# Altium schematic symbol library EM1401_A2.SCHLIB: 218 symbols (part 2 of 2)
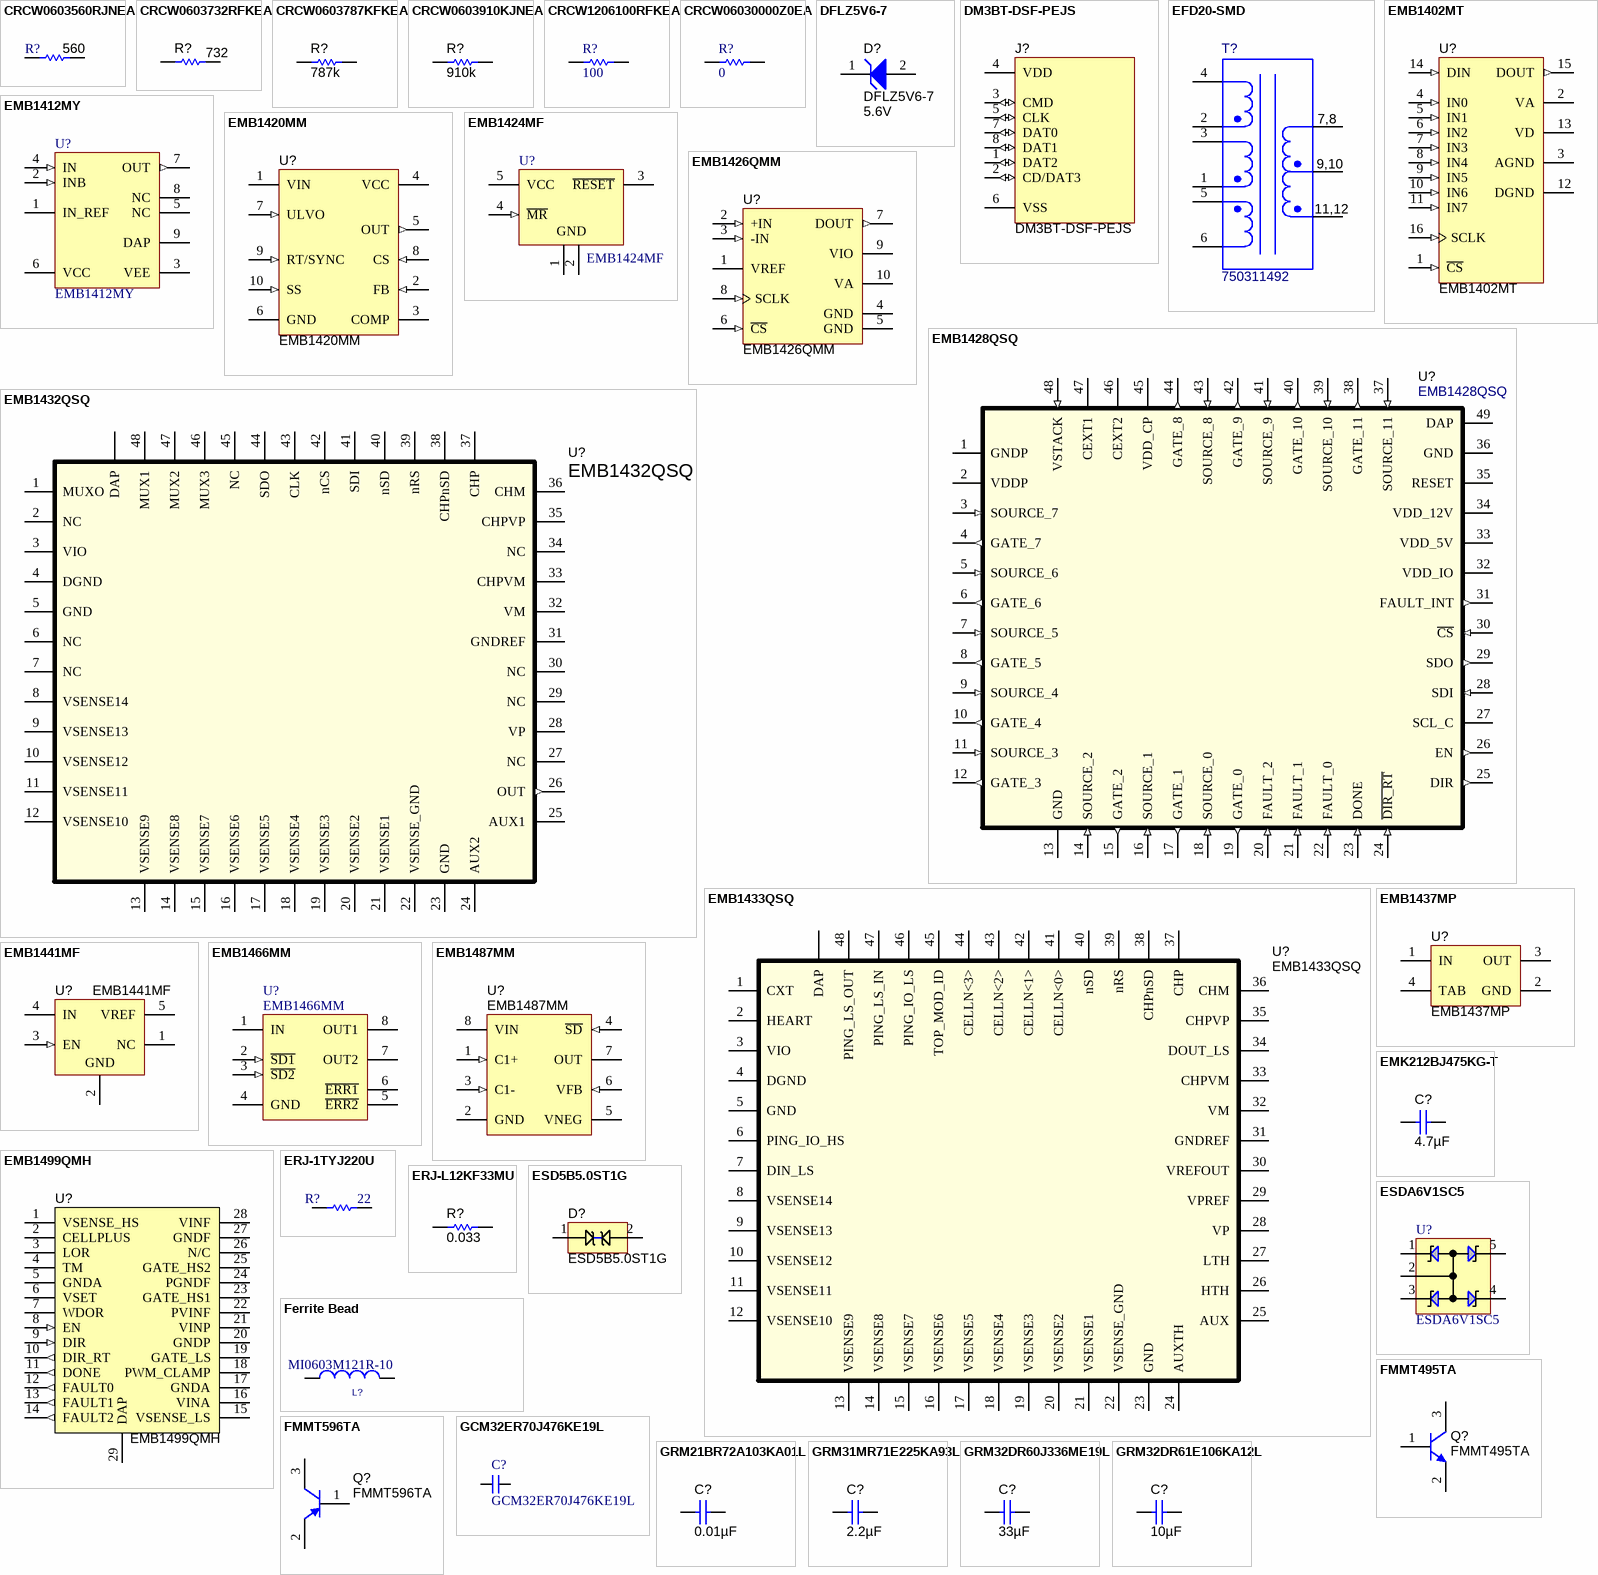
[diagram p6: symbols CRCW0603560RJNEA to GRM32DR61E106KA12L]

## EMB1433QSQ
designator U?
Battery Stack Protection WCOMP; Manufacturer: National Semiconductor; CompType: Used in BOM report; SymbolVersion: 100509; SymbolCreator: cwiosc
footprint sqa48b (QFN, 48-Leads, Body 7x7mm, Pitch 0.5mm, NSC Recommended)
pins: 1 CXT, 2 HEART, 3 VIO, 4 DGND, 5 GND, 6 PING_IO_HS, 7 DIN_LS, 8 VSENSE14, 9 VSENSE13, 10 VSENSE12, 11 VSENSE11, 12 VSENSE10, 13 VSENSE9, 14 VSENSE8, 15 VSENSE7, 16 VSENSE6, 17 VSENSE5, 18 VSENSE4, 19 VSENSE3, 20 VSENSE2, 21 VSENSE1, 22 VSENSE_GND, 23 GND, 24 AUXTH, 25 AUX, 26 HTH, 27 LTH, 28 VP, 29 VPREF, 30 VREFOUT, 31 GNDREF, 32 VM, 33 CHPVM, 34 DOUT_LS, 35 CHPVP, 36 CHM, 37 CHP, 38 CHPnSD, 39 nRS, 40 nSD, 41 CELLN<0>, 42 CELLN<1>, 43 CELLN<2>, 44 CELLN<3>, 45 TOP_MOD_ID, 46 PING_IO_LS, 47 PING_LS_IN, 48 PING_LS_OUT, 49 DAP

## EMB1437MP
designator U?
500 mA Low Dropout Regulator; Manufacturer: National Semiconductor; CompType: LDO IC; PowerWise: N
footprint MP04A_N (SOT223, 4-Leads, Body 6.5x3.5mm, Pitch 2.3mm, Lead Span 7mm, IPC Medium Density)
footprint MP04A_L (SOT223, 4-Leads, Body 6.5x3.5mm, Pitch 2.3mm, Lead Span 7mm, IPC High Density)
footprint MP04A_M (SOT223, 4-Leads, Body 6.5x3.5mm, Pitch 2.3mm, Lead Span 7mm, IPC Low Density)
pins: 1 IN (power), 2 GND (power), 3 OUT (power), 4 TAB (power)

## EMB1441MF
designator U?
SOT-23 Precision Low Dropout Voltage Reference; Manufacturer: National Semiconductor; CompType: Voltage Reference IC; PowerWise: Y
footprint MF05A_N (SOT23, 5-Leads, Body 2.9x1.6mm, Pitch 0.95mm, Lead Span 2.8mm, IPC Medium Density)
footprint MF05A_L (SOT23, 5-Leads, Body 2.9x1.6mm, Pitch 0.95mm, Lead Span 2.8mm, IPC High Density)
footprint MF05A_M (SOT23, 5-Leads, Body 2.9x1.6mm, Pitch 0.95mm, Lead Span 2.8mm, IPC Low Density)
pins: 1 NC, 2 GND (power), 3 EN (in), 4 IN (power), 5 VREF (power)

## EMB1466MM
designator U?
Dual 150mA Ultra Low-Dropout Regulator; Manufacturer: National Semiconductor; CompType: LDO IC; PowerWise: N
footprint MUA08A_N (TSOP, 8-Leads, Body 3x3mm, Pitch 0.65mm, IPC Medium Density)
footprint MUA08A_L (TSOP, 8-Leads, Body 3x3mm, Pitch 0.65mm, IPC High Density)
footprint MUA08A_M (TSOP, 8-Leads, Body 3x3mm, Pitch 0.65mm, IPC Low Density)
pins: 1 IN (power), 2 ~{SD1} (in), 3 ~{SD2} (in), 4 GND (power), 5 ~{ERR2} (oc), 6 ~{ERR1} (oc), 7 OUT2 (power), 8 OUT1 (power)

## EMB1487MM
designator U?
Low Noise Regulated Switched Capacitor Voltage Inverter; Manufacturer: National Semiconductor; CompType: Switch Caps; PowerWise: N
footprint MUA08A_N (TSOP, 8-Leads, Body 3x3mm, Pitch 0.65mm, IPC Medium Density)
footprint MUA08A_L (TSOP, 8-Leads, Body 3x3mm, Pitch 0.65mm, IPC High Density)
footprint MUA08A_M (TSOP, 8-Leads, Body 3x3mm, Pitch 0.65mm, IPC Low Density)
pins: 1 C1+ (in), 2 GND (power), 3 C1- (in), 4 ~{SD} (in), 5 VNEG (power), 6 VFB (in), 7 OUT (power), 8 VIN (power)

## EMB1499QMH
designator U?
PWM Controller; Manufacturer: National Semiconductor; CompType: Used in BOM report; SymbolVersion: use current date i.e. 2008-05-20; SymbolCreator: Use LDAP id
footprint MXA28A_M (TSOP, 28-Leads, Body 9.7x4.4mm, Pitch 0.65mm, Exposed Pad, IPC Low Density)
pins: 1 VSENSE_HS, 2 CELLPLUS, 3 LOR, 4 TM, 5 GNDA, 6 VSET, 7 WDOR, 8 EN (in), 9 DIR (in), 10 DIR_RT (out), 11 DONE (out), 12 FAULT0 (out), 13 FAULT1 (out), 14 FAULT2 (out), 15 VSENSE_LS, 16 VINA, 17 GNDA, 18 PWM_CLAMP, 19 GATE_LS, 20 GNDP, 21 VINP, 22 PVINF, 23 GATE_HS1, 24 PGNDF, 25 GATE_HS2, 26 N/C, 27 GNDF, 28 VINF, 29 DAP

## EMK212BJ475KG-T
designator C?  value 4.7µF  (hidden comment: EMK212BJ475KG-T)
CAP, CERM, 4.7µF, 16V, +/-10%, X5R, 0805; Manufacturer: Taiyo Yuden; Cap_Case: 0805; Polarized: N; TaMax_C: 85; TaMin_C: -55; Tolerance_%: 10; VDC_V: 16; Cap_F: 4.7E-6; CompType: Capacitor
signal-integrity model Cap
simulation model Cap
footprint 0805_HV
footprint 0805
footprint 0805M
footprint 0805L
pins: 1, 2

## ERJ-1TYJ220U
designator R?  value 22  (hidden comment: ERJ-1TYJ220U)
22 Ohm 1%, 1W; Manufacturer: Panasonic; CompType: Resistor; Tolerance_%: 1; Res_Ohm: 100; Value_Code: R020; EIA_Code: ERJ
signal-integrity model Resistor
simulation model Resistor
footprint 2512M (Chip Resistor, Body 6.3x3.2mm, IPC Low Density)
footprint 2010L
footprint 2010
pins: 1, 2

## ERJ-L12KF33MU
designator R?  value 0.033  (hidden comment: ERJ-L12KF33MU)
RES, 0.033 ohm, 1%, 0.5W, 1812 SMD; Manufacturer: Panasonic; CompType: Resistor; Tolerance_%: 1; Power_W: 0.5; Value_Code: R033; EIA_Code: E96
signal-integrity model Resistor
simulation model Resistor
footprint 1812M
footprint 1812L
footprint 1812
pins: 1, 2

## ESD5B5.0ST1G
designator D?
TVS ESD BIDIRECT 5V SOD523; Manufacturer: ON Semiconductor; SymbolVersion: use current date i.e. 2008-05-20; SymbolCreator: Use LDAP id
footprint SOD523 TVS (SOD footpirnt - TVS ESD Bidirectional)
pins: 1, 2

## ESDA6V1SC5
designator U?
DIODE ARRAY ESD 6.1V Breakdown; Manufacturer: STMicroelectronics; CompType: ESD protection
footprint MF05A_M (SOT23, 5-Leads, Body 2.9x1.6mm, Pitch 0.95mm, Lead Span 2.8mm, IPC Low Density)
pins: 1 IO1, 2 IO2, 3 IO3, 4 IO4, 5 IO5

## Ferrite Bead
designator L?, comment MI0603M121R-10
Ferrite bead, 120mOhm, 2A, 0603; Manufacturer: Steward
footprint 0603
pins: 1, 2

## FMMT495TA
designator Q?
NPN, 1A, 150V; Manufacturer: Diodes Inc.; CompType: BJT; IcRated_A: 1; Vceo_V: 150; Vcesat1_V: 0.2; Value: 0.2V; PNP: 0
footprint SOT-23 (SOT23, 3-Leads, Body 2.9x1.3mm, Pitch 0.95mm, Lead Span 2.5mm, IPC Medium Density)
pins: 1 B, 2 E, 3 C

## FMMT596TA
designator Q?
PNP, 1.4A, 100V; Manufacturer: Diodes Inc; CompType: BJT; IcRated_A: 0.3; Vceo_V: 200; Vcesat1_V: 0.2; Value: 0.2V; PNP: 1; NPN: 0; Value1: 0.3A
footprint SOT-23 (SOT23, 3-Leads, Body 2.9x1.3mm, Pitch 0.95mm, Lead Span 2.5mm, IPC Medium Density)
pins: 1 B, 2 E, 3 C

## GCM32ER70J476KE19L
designator C?
CAP CER 47UF 6.3V X7R 1210; Manufacturer: Murata; CompType: Capacitor X7R
footprint 1210 (1210 STANDARD SIZE)
pins: 1, 2

## GRM21BR72A103KA01L
designator C?  ValueDisplayed: 0.01µF  (hidden comment: GRM21BR72A103KA01L)
CAP, CERM, 0.01uF, 100V, +/-10%, X7R, 0805; Manufacturer: MuRata; Cap_Case: 0805; Polarized: N; TaMax_C: 125; TaMin_C: -55; Tolerance_%: 10; VDC_V: 100; Cap_F: 0.00000001; CompType: Capacitor; U/M: EA
signal-integrity model Cap
simulation model Cap
footprint 0805_HV
footprint 0805
footprint 0805M
footprint 0805L
pins: 1, 2

## GRM31MR71E225KA93L
designator C?  ValueDisplayed: 2.2µF  (hidden comment: GRM31MR71E225KA93L)
CAP, CERM, 2.2uF, 25V, +/-10%, X7R, 1210; Manufacturer: MuRata; Cap_Case: 1210; Polarized: N; TaMax_C: 125; TaMin_C: -55; Tolerance_%: 10; VDC_V: 25; Cap_F: 0.0000022; CompType: Capacitor; U/M: EA
signal-integrity model Cap
simulation model Cap
footprint 1210
footprint 1210M
footprint 1210L
pins: 1, 2

## GRM32DR60J336ME19L
designator C?  ValueDisplayed: 33µF  (hidden comment: GRM32DR60J336ME19L)
CAP, CERM, 33uF, 6.3V, +/-20%, X5R, 1210; Manufacturer: MuRata; Cap_Case: 1210; ESR_Ohm: 0.006; Polarized: N; TaMax_C: 85; TaMin_C: -55; Tolerance_%: 20; VDC_V: 6.3; Cap_F: 0.000033; CompType: Capacitor; U/M: EA; Value1: 0.006 ohm
signal-integrity model Cap
simulation model Cap
footprint 1210
footprint 1210M
footprint 1210L
pins: 1, 2

## GRM32DR61E106KA12L
designator C?  ValueDisplayed: 10µF  (hidden comment: GRM32DR61E106KA12L)
CAP, CERM, 10uF, 25V, +/-10%, X5R, 1210; Manufacturer: MuRata; Cap_Case: 1210; Polarized: N; TaMax_C: 85; TaMin_C: -55; Tolerance_%: 10; VDC_V: 25; Cap_F: 0.00001; CompType: Capacitor; U/M: EA
signal-integrity model Cap
simulation model Cap
footprint 1210
footprint 1210M
footprint 1210L
pins: 1, 2

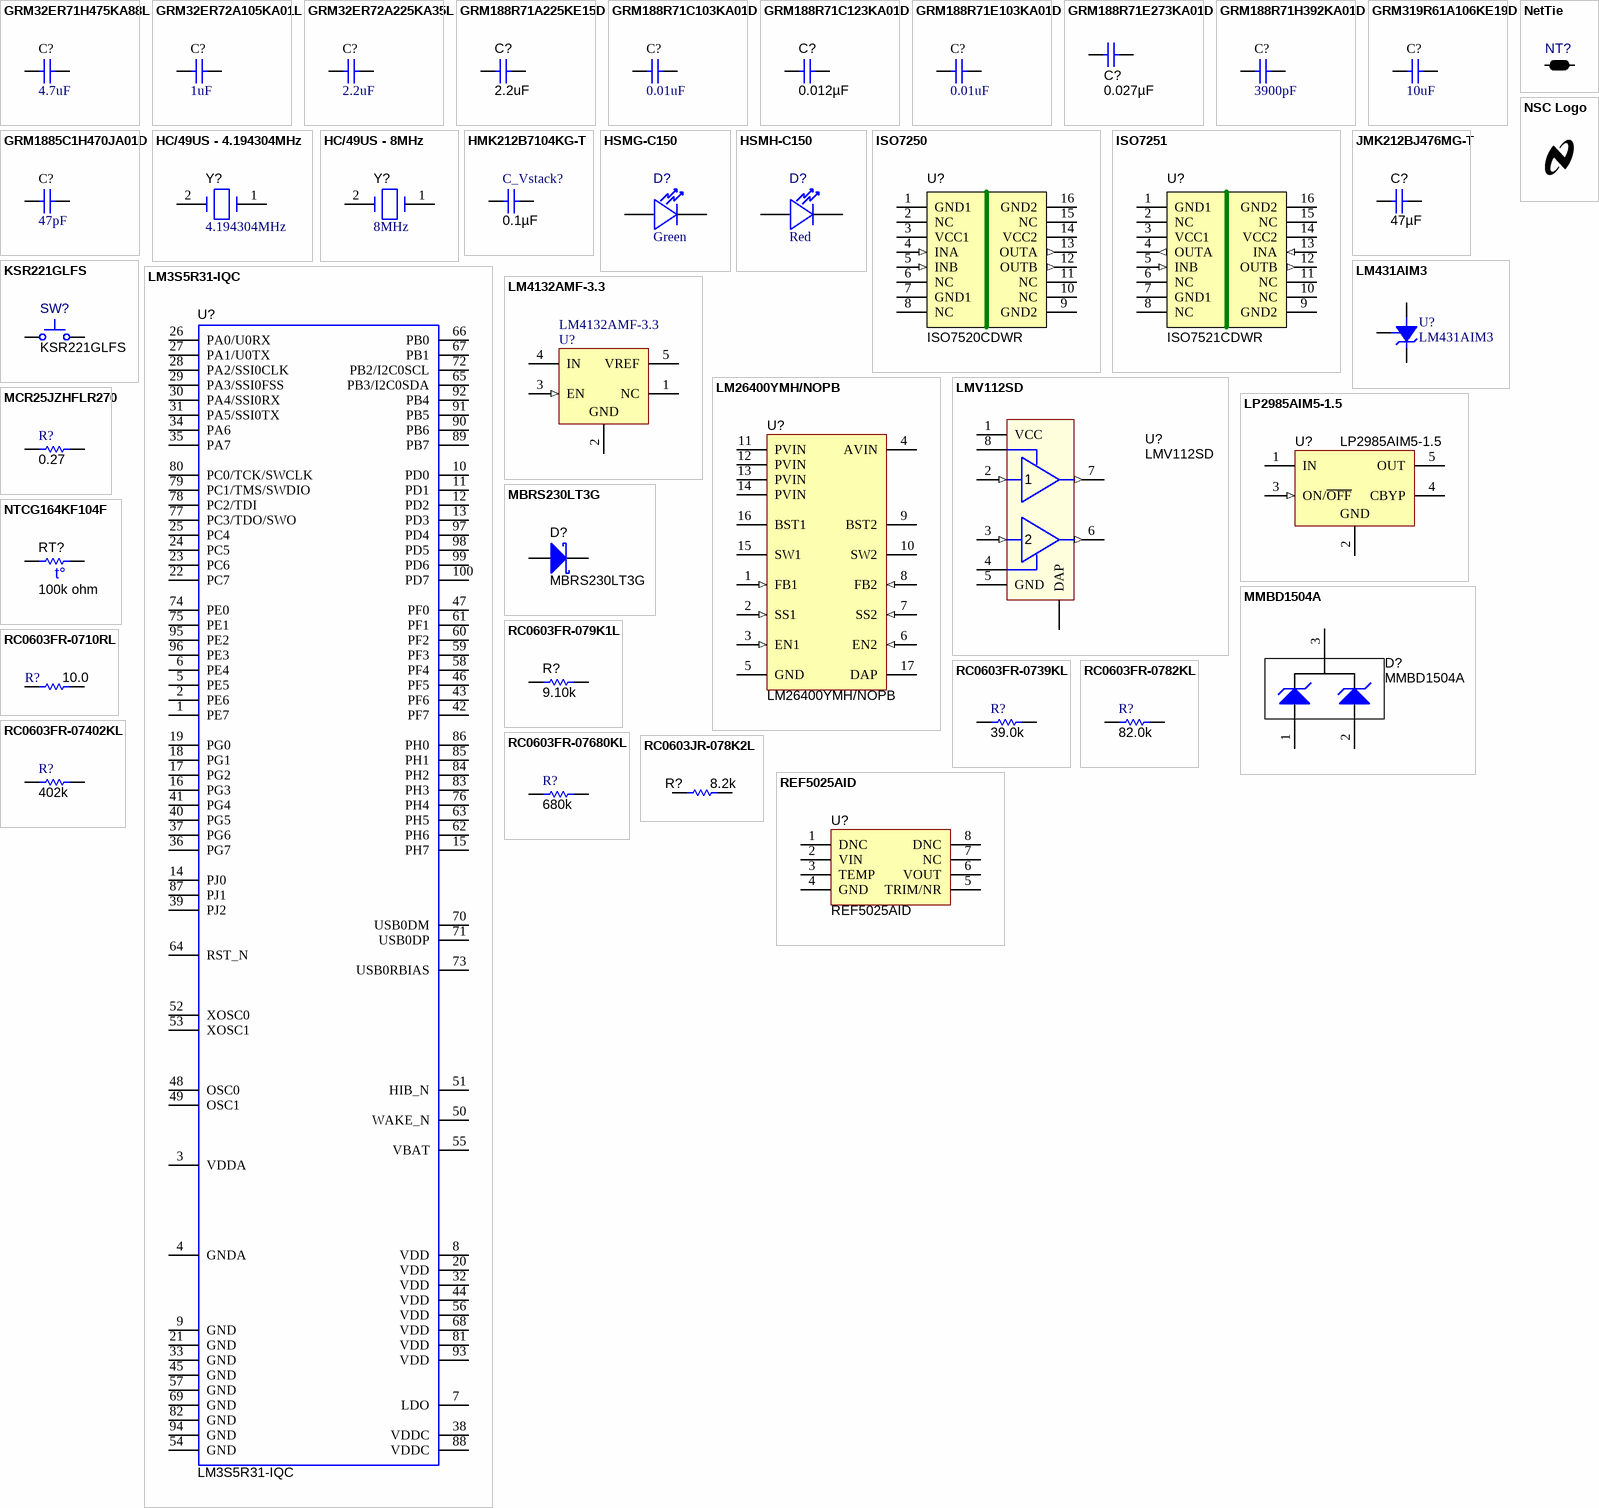
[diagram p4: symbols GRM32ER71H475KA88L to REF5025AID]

## GRM32ER71H475KA88L
designator C?  value 4.7uF  (hidden comment: GRM32ER71H475KA88L)
Ceramic, X7R, 50V, 10%; Manufacturer: MuRata; Cap_Case: 1210; ESR_Ohm: 0.002; Polarized: N; TaMax_C: 125; TaMin_C: -55; Tolerance_%: 10; VDC_V: 50; Cap_F: 4.7E-6; CompType: Capacitor; Value1: 0.002 Ohm
signal-integrity model Cap
simulation model Cap
footprint 1210
footprint 1210M
footprint 1210L
pins: 1, 2

## GRM32ER72A105KA01L
designator C?  value 1uF  (hidden comment: GRM32ER72A105KA01L)
Ceramic, X7R, 100V, 10%; Manufacturer: MuRata; Cap_Case: 1210; Polarized: N; TaMax_C: 125; TaMin_C: -55; Tolerance_%: 10; VDC_V: 100; Cap_F: 1.0E-6; CompType: Capacitor
signal-integrity model Cap
simulation model Cap
footprint 1210
footprint 1210M
footprint 1210L
pins: 1, 2

## GRM32ER72A225KA35L
designator C?  value 2.2uF  (hidden comment: GRM32ER72A225KA35L)
Ceramic, X7R, 100V, 10%; Manufacturer: MuRata; Cap_Case: 1210; ESR_Ohm: 0.007; IRMS_A: 4.4; Polarized: N; TaMax_C: 125; TaMin_C: -55; Tolerance_%: 10; VDC_V: 100; Cap_F: 2.2E-6; CompType: Capacitor; Value1: 0.007 Ohm
signal-integrity model Cap
simulation model Cap
footprint 1210
footprint 1210M
footprint 1210L
pins: 1, 2

## GRM188R71A225KE15D
designator C?  value 2.2uF  (hidden comment: GRM188R71A225KE15D)
Ceramic, X7R, 10V, 10%; Manufacturer: MuRata; Cap_Case: 0603; ESR_Ohm: 0.009; Polarized: N; TaMax_C: 125; TaMin_C: -55; Tolerance_%: 10; Cap_F: 2.2E-6; CompType: Capacitor; Value1: 0.009 Ohm
signal-integrity model Cap
simulation model Cap
footprint 0603
footprint 0603M
footprint 0603L (0603 from SM-752 data)
footprint 0603_HV
pins: 1, 2

## GRM188R71C103KA01D
designator C?  value 0.01uF  (hidden comment: GRM188R71C103KA01D)
Ceramic, X7R, 16V, 10%; Manufacturer: MuRata; Cap_Case: 0603; Polarized: N; TaMax_C: 125; TaMin_C: -55; Tolerance_%: 10; VDC_V: 16; Cap_F: 10.0E-9; CompType: Capacitor
signal-integrity model Cap
simulation model Cap
footprint 0603
footprint 0603M
footprint 0603L (0603 from SM-752 data)
pins: 1, 2

## GRM188R71C123KA01D
designator C?  ValueDisplayed: 0.012µF  (hidden comment: GRM188R71C123KA01D)
CAP, CERM, 0.012uF, 16V, +/-10%, X7R, 0603; Manufacturer: MuRata; Cap_Case: 0603; Polarized: N; TaMax_C: 125; TaMin_C: -55; Tolerance_%: 10; VDC_V: 16; Cap_F: 0.000000012; CompType: Capacitor; U/M: EA
signal-integrity model Cap
simulation model Cap
footprint 0603
footprint 0603M
footprint 0603L
footprint 0603_HV
pins: 1, 2

## GRM188R71E103KA01D
designator C?  value 0.01uF  (hidden comment: GRM188R71E103KA01D)
Ceramic, X7R, 25V, 10%; Manufacturer: MuRata; Cap_Case: 0603; Polarized: N; TaMax_C: 125; TaMin_C: -55; Tolerance_%: 10; VDC_V: 25; Cap_F: 10.0E-9; CompType: Capacitor
signal-integrity model Cap
simulation model Cap
footprint 0603
footprint 0603M
footprint 0603L (0603 from SM-752 data)
footprint 0603_HV
pins: 1, 2

## GRM188R71E273KA01D
designator C?  ValueDisplayed: 0.027µF  (hidden comment: GRM188R71E273KA01D)
CAP, CERM, 0.027uF, 25V, +/-10%, X7R, 0603; Manufacturer: MuRata; Alternate PartNumber: 06035C273KAT2A; Alternate Manufacturer: AVX; Cap_Case: 0603; Polarized: N; TaMax_C: 125; TaMin_C: -55; Tolerance_%: 10; VDC_V: 25; Cap_F: 0.000000027; CompType: Capacitor; U/M: EA
signal-integrity model Cap
simulation model Cap
footprint 0603
footprint 0603M
footprint 0603L
footprint 0603_HV
pins: 1, 2

## GRM188R71H392KA01D
designator C?  value 3900pF  (hidden comment: GRM188R71H392KA01D)
Ceramic, X7R, 50V, 10%; Manufacturer: MuRata; Cap_Case: 0603; Polarized: N; TaMax_C: 125; TaMin_C: -55; Tolerance_%: 10; VDC_V: 50; Cap_F: 3.9E-9; CompType: Capacitor
signal-integrity model Cap
simulation model Cap
footprint 0603
footprint 0603M
footprint 0603L (0603 from SM-752 data)
footprint 0603_HV
pins: 1, 2

## GRM319R61A106KE19D
designator C?  value 10uF  (hidden comment: GRM319R61A106KE19D)
Ceramic, X5R, 10V, 10%; Manufacturer: MuRata; Cap_Case: 1206; ESR_Ohm: 0.004; Polarized: N; TaMax_C: 85; TaMin_C: -55; Tolerance_%: 10; Cap_F: 10.0E-6; CompType: Capacitor; Value1: 0.004 Ohm
signal-integrity model Cap
simulation model Cap
footprint 1206
footprint 1206M
footprint 1206L
pins: 1, 2

## GRM1885C1H470JA01D
designator C?  value 47pF  (hidden comment: GRM1885C1H470JA01D)
Ceramic, C0G/NP0, 50V, 5%; Manufacturer: MuRata; Cap_Case: 0603; Polarized: N; TaMax_C: 125; TaMin_C: -55; Tolerance_%: 5; VDC_V: 50; Cap_F: 47.0E-12; CompType: Capacitor
signal-integrity model Cap
simulation model Cap
footprint 0603
footprint 0603M
footprint 0603L (0603 from SM-752 data)
pins: 1, 2

## HC/49US - 4.194304MHz
designator Y?, comment value 4.194304MHz  (hidden comment: ABLSG-4.194304MHZ-D-2-Y-T)
SMD Low Profile Crystal; Manufacturer: Abracon Corporation; CompType: Oscillator; Drive Level: 1mW; Value1: 18pf
footprint HC-49US crystal
pins: 1, 2

## HC/49US - 8MHz
designator Y?, comment value 8MHz  (hidden comment: ABLS2-8.000MHZ-D4Y-T)
SMD Low Profile Crystal; Manufacturer: Abracon Corporation; CompType: Oscillator; Drive Level: 1mW; Value1: 18pf
footprint HC-49US crystal
pins: 1, 2

## HMK212B7104KG-T
designator C_Vstack?  ValueDisplayed: 0.1µF  (hidden comment: HMK212B7104KG-T)
CAP, CERM, 0.1uF, 100V, +/-10%, X7R, 0805; Manufacturer: Taiyo Yuden; Cap_Case: 0805; Polarized: N; TaMax_C: 125; TaMin_C: -55; Tolerance_%: 10; VDC_V: 100; Cap_F: 100.0E-9; CompType: Capacitor
signal-integrity model Cap
simulation model Cap
footprint 0805_HV
footprint 0805
footprint 0805M
footprint 0805L
pins: 1, 2

## HSMG-C150
designator D?  value Green  (hidden comment: HSMG-C150)
LED 570NM GREEN DIFF 1206 SMD; Manufacturer: Avago Technologies; SymbolVersion: 06-2009; SymbolCreator: Use LDAP id
footprint HSMG-xxx (1206 LED for HSM series Avago Techlonogies SMT LED)
pins: 1 Anode, 2 Cathode

## HSMH-C150
designator D?  value Red  (hidden comment: HSMH-C150)
LED 660NM RED DIFF 1206 SMD; Manufacturer: Avago Technologies; SymbolVersion: 06-2009; SymbolCreator: Use LDAP id
footprint HSMH-xxx (1206 LED for HSM series Avago Techlonogies SMT LED)
pins: 1 Anode, 2 Cathode

## ISO7250
designator U?, comment ISO7520CDWR
Low Power 3-Channel Digital Isolator; Manufacturer: TI
footprint SOIC16 Wide (SOIC, 16-Leads, Body 10.3x7.5mm, Pitch 1.27mm, wide for isolation)
pins: 1 GND1 (power), 2 NC, 3 VCC1 (power), 4 INA (in), 5 INB (in), 6 NC, 7 GND1 (power), 8 NC, 9 GND2 (power), 10 NC, 11 NC, 12 OUTB (out), 13 OUTA (out), 14 VCC2 (power), 15 NC, 16 GND2 (power)

## ISO7251
designator U?, comment ISO7521CDWR
Low Power 3-Channel Digital Isolator; Manufacturer: TI
footprint SOIC16 Wide (SOIC, 16-Leads, Body 10.3x7.5mm, Pitch 1.27mm, wide for isolation)
pins: 1 GND1 (power), 2 NC, 3 VCC1 (power), 4 OUTA (out), 5 INB (in), 6 NC, 7 GND1 (power), 8 NC, 9 GND2 (power), 10 NC, 11 NC, 12 OUTB (out), 13 INA (in), 14 VCC2 (power), 15 NC, 16 GND2 (power)

## JMK212BJ476MG-T
designator C?  ValueDisplayed: 47µF  (hidden comment: JMK212BJ476MG-T)
CAP, CERM, 47uF, 6.3V, +/-20%, X5R, 0805; Manufacturer: Taiyo Yuden; Cap_Case: 0805; Polarized: N; TaMax_C: 85; TaMin_C: -55; Tolerance_%: 20; VDC_V: 6.3; Cap_F: 0.000047; CompType: Capacitor; U/M: EA
signal-integrity model Cap
simulation model Cap
footprint 0805_HV
footprint 0805
footprint 0805M
footprint 0805L
pins: 1, 2

## KSR221GLFS
designator SW?
Switch, Normally open, 2.3N force, 200k operations, SMD; Manufacturer: C&K Components; CompType: SPST Switch
footprint KSR (C&K Components SPST switch)
pins: 1, 2

## LM3S5R31-IQC
designator U?
Stellaris ARM Cortex-M3 Microcontroller; PartNumber: LM3S5R31-IQC-C5; Manufacturer: Texas Instruments; Stellaris Class: Tempest
footprint QFP50P1600X1600X160-100N
pins: 1 PE7, 2 PE6, 3 VDDA, 4 GNDA, 5 PE5, 6 PE4, 7 LDO, 8 VDD, 9 GND, 10 PD0, 11 PD1, 12 PD2, 13 PD3, 14 PJ0, 15 PH7, 16 PG3, 17 PG2, 18 PG1, 19 PG0, 20 VDD, 21 GND, 22 PC7, 23 PC6, 24 PC5, 25 PC4, 26 PA0/U0RX, 27 PA1/U0TX, 28 PA2/SSI0CLK, 29 PA3/SSI0FSS, 30 PA4/SSI0RX, 31 PA5/SSI0TX, 32 VDD, 33 GND, 34 PA6, 35 PA7, 36 PG7, 37 PG6, 38 VDDC, 39 PJ2, 40 PG5, 41 PG4, 42 PF7, 43 PF6, 44 VDD, 45 GND, 46 PF5, 47 PF0, 48 OSC0, 49 OSC1, 50 WAKE_N, 51 HIB_N, 52 XOSC0, 53 XOSC1, 54 GND, 55 VBAT, 56 VDD, 57 GND, 58 PF4, 59 PF3, 60 PF2, 61 PF1, 62 PH6, 63 PH5, 64 RST_N, 65 PB3/I2C0SDA, 66 PB0, 67 PB1, 68 VDD, 69 GND, 70 USB0DM, 71 USB0DP, 72 PB2/I2C0SCL, 73 USB0RBIAS, 74 PE0, 75 PE1, 76 PH4, 77 PC3/TDO/SWO, 78 PC2/TDI, 79 PC1/TMS/SWDIO, 80 PC0/TCK/SWCLK, 81 VDD, 82 GND, 83 PH3, 84 PH2, 85 PH1, 86 PH0, 87 PJ1, 88 VDDC, 89 PB7, 90 PB6, 91 PB5, 92 PB4, 93 VDD, 94 GND, 95 PE2, 96 PE3, 97 PD4, 98 PD5, 99 PD6, 100 PD7

## LM431AIM3
designator U?
Adjustable Precision Zener Shunt Regulator; Manufacturer: National Semiconductor; CompType: MiscPower; PackageTopMarking: N1E*XTT
footprint MF03A_N (SOT23, 3-Leads, Body 2.9x1.3mm, Pitch 0.95mm, Lead Span 2.4mm, IPC Medium Density)
footprint MF03A_L (SOT23, 3-Leads, Body 2.9x1.3mm, Pitch 0.95mm, Lead Span 2.4mm, IPC High Density)
footprint MF03A_M (SOT23, 3-Leads, Body 2.9x1.3mm, Pitch 0.95mm, Lead Span 2.4mm, IPC Low Density)
pins: 1 K, 2 REF, 3 A

## LM4132AMF-3.3
designator U?
SOT-23 Precision Low Dropout Voltage Reference; Manufacturer: National Semiconductor; CompType: Voltage Reference IC; PackageTopMarking: R4EA*XTT; PowerWise: N
footprint MF05A_N (SOT23, 5-Leads, Body 2.9x1.6mm, Pitch 0.95mm, Lead Span 2.8mm, IPC Medium Density)
footprint MF05A_L (SOT23, 5-Leads, Body 2.9x1.6mm, Pitch 0.95mm, Lead Span 2.8mm, IPC High Density)
footprint MF05A_M (SOT23, 5-Leads, Body 2.9x1.6mm, Pitch 0.95mm, Lead Span 2.8mm, IPC Low Density)
pins: 1 NC, 2 GND (power), 3 EN (in), 4 IN (power), 5 VREF (power)

## LM26400YMH/NOPB
designator U?
Dual 2A, 500kHz Wide Input Range Buck Regulator, 16-pin TSSOP-EP, Pb-Free; Manufacturer: National Semiconductor; PackageTopMarking: NSUZXYTT*L26400*YMH; PowerWise: N; CompType: Switcher
footprint MXA16A_N (TSOP, 16-Leads, Body 5x4.4mm, Pitch 0.65mm, Exposed Pad, IPC Medium Density)
footprint MXA16A_L (TSOP, 16-Leads, Body 5x4.4mm, Pitch 0.65mm, Exposed Pad, IPC High Density)
footprint MXA16A_M (TSOP, 16-Leads, Body 5x4.4mm, Pitch 0.65mm, Exposed Pad, IPC Low Density)
pins: 1 FB1 (in), 2 SS1 (in), 3 EN1 (in), 4 AVIN (power), 5 GND (power), 6 EN2 (in), 7 SS2 (in), 8 FB2 (in), 9 BST2, 10 SW2 (power), 11 PVIN (power), 12 PVIN (power), 13 PVIN (power), 14 PVIN (power), 15 SW1 (power), 16 BST1, 17 DAP (power)

## LMV112SD
designator U?
40MHz Dual Clock Buffer; Manufacturer: National Semiconductor; Characteristics: LMV112 40MHz Dual Clock Buffer; CompType: Buffer IC; TaMin_C: -40.0; TaMax_C: 85.0
3D model SDA08A (PCB3D Model)
footprint SDA08A (SON, 8-Leads, Body 3x3mm, Pitch 0.5mm, NSC Recommended)
pins: 1 VCC (power), 2 IN1 (in), 3 IN2 (in), 4 EN2, 5 GND (power), 6 OUT2 (out), 7 OUT1 (out), 8 EN1, 9 DAP

## LP2985AIM5-1.5
designator U?
Micropower 150 mA Low-Noise Ultra Low-Dropout Regulator, 5-pin SOT-23; Manufacturer: National Semiconductor; PackageTopMarking: LCHA*XTT; PowerWise: N; CompType: LDO IC
footprint MF05A_N (SOT23, 5-Leads, Body 2.9x1.6mm, Pitch 0.95mm, Lead Span 2.8mm, IPC Medium Density)
footprint MF05A_L (SOT23, 5-Leads, Body 2.9x1.6mm, Pitch 0.95mm, Lead Span 2.8mm, IPC High Density)
footprint MF05A_M (SOT23, 5-Leads, Body 2.9x1.6mm, Pitch 0.95mm, Lead Span 2.8mm, IPC Low Density)
pins: 1 IN (power), 2 GND (power), 3 ON/~{OFF} (in), 4 CBYP, 5 OUT (power)

## MBRS230LT3G
designator D?
DIODE 2A 30V SMB; Manufacturer: ON Semiconductor; CompType: Zener; SymbolCreator: CSXHSC
footprint SMB (Molded Diode, 2-Leads, Body 5.4x3.6mm, IPC Medium Density, based on OnSemi component dimensions)
pins: 1 A, 2 K

## MCR25JZHFLR270
designator R?  value 0.27  (hidden comment: MCR25JZHFLR270)
RES, 0.27 ohm, 1%, 0.5W, 1210 SMD; Manufacturer: Rohm; CompType: Resistor; Tolerance_%: 1; VDC_V: 0; Power_W: 0.5; Value_Code: R270; EIA_Code: E96
signal-integrity model Resistor
simulation model Resistor
footprint 1210M
footprint 1210L
footprint 1210
pins: 1, 2

## MMBD1504A
designator D?
Diode, Dual, 200V, 350mW, SOT-23; Manufacturer: Fairchild Semiconductor; CompType: Zener; Power_W: 0.350; Ct: 4pF; Value1: 0.350W; RJA_CperW: 556
signal-integrity model Diode
footprint SOT-23
pins: 1 A1, 2 A2, 3 K

## NetTie
designator NT?  (net tie, no BOM)
Value1: DNP
footprint 0603_NET_TIE (Net tie.)
pins: 1, 2

## NSC Logo
designator Logo?, comment PCB Logo  (value not drawn)  (no BOM)
National Semiconductor logo or worldmark; SymbolCreator: codlsc
footprint Logo_CopperSolderMask_Large
footprint Logo_CopperSolderMask_Medium
footprint Logo_CopperSolderMask_Small
footprint Logo_Overlay_Large
footprint Logo_Overlay_Medium
footprint Logo_Overlay_Small
footprint Logo_Copper_Large
footprint Logo_Copper_Medium
footprint Logo_Copper_Small
footprint Logo_SolderMask_Large
footprint Logo_SolderMask_Medium
footprint Logo_SolderMask_Small
footprint Worldmark_CopperSolderMask_Medium
footprint Worldmark_CopperSolderMask_Small
footprint Worldmark_Overlay_Medium
footprint Worldmark_Overlay_Small
footprint Worldmark_Copper_Medium
footprint Worldmark_Copper_Small
footprint Worldmark_SolderMask_Medium
footprint Worldmark_SolderMask_Small

## NTCG164KF104F
designator RT?  value 100k ohm  (hidden comment: NTCG164KF104F)
Thermistor NTC, 100k ohm, 1%, 0603; Manufacturer: TDK; Tolerance_%: 1; TaMin_C: -40; TaMax_C: 125
footprint 0603
footprint 0603M
footprint 0603L
footprint 0603_HV
pins: 1, 2

## RC0603FR-079K1L
designator R?  value 9.10k  (hidden comment: RC0603FR-079K1L)
RES, 9.10k ohm, 1%, 0.1W, 0603; Manufacturer: Yageo America; CompType: Resistor; Tolerance_%: 1; VDC_V: 150; Power_W: 0.1; Res_ohm: 9100; TempCo_ppm/C: 200; Value_Code: 9k10; U/M: EA
signal-integrity model Resistor
simulation model Resistor
footprint 0603
footprint 0603M
footprint 0603L
footprint 0603_HV
pins: 1, 2

## RC0603FR-0710RL
designator R?  value 10.0  (hidden comment: RC0603FR-0710RL)
RES, 10.0 ohm, 1%, 0.1W, 0603; Manufacturer: Yageo America; CompType: Resistor; Tolerance_%: 1; VDC_V: 150; Power_W: 0.1; Res_Ohm: 10; Value_Code: 10R0; EIA_Code: E96
signal-integrity model Resistor
simulation model Resistor
footprint 0603
footprint 0603M
footprint 0603L
footprint 0603_HV
pins: 1, 2

## RC0603FR-0739KL
designator R?  value 39.0k  (hidden comment: RC0603FR-0739KL)
RES, 39.0k ohm, 1%, 0.1W, 0603; Manufacturer: Yageo America; CompType: Resistor; Tolerance_%: 1; VDC_V: 150; Power_W: 0.1; Res_ohm: 39000; Value_Code: 39k0; TempCo_ppm/C: 200; U/M: EA
signal-integrity model Resistor
simulation model Resistor
footprint 0603
footprint 0603M
footprint 0603L
footprint 0603_HV
pins: 1, 2

## RC0603FR-0782KL
designator R?  value 82.0k  (hidden comment: RC0603FR-0782KL)
RES, 82.0k ohm, 1%, 0.1W, 0603; Manufacturer: Yageo America; CompType: Resistor; Tolerance_%: 1; VDC_V: 150; Power_W: 0.1; Res_ohm: 82000; Value_Code: 82k0; TempCo_ppm/C: 200; U/M: EA
signal-integrity model Resistor
simulation model Resistor
footprint 0603
footprint 0603M
footprint 0603L
footprint 0603_HV
pins: 1, 2

## RC0603FR-07402KL
designator R?  value 402k  (hidden comment: RC0603FR-07402KL)
RES, 402k ohm, 1%, 0.1W, 0603; Manufacturer: Yageo America; CompType: Resistor; Tolerance_%: 1; VDC_V: 150; Power_W: 0.1; Res_ohm: 402000; EIA_Code: E96; U/M: EA
signal-integrity model Resistor
simulation model Resistor
footprint 0603
footprint 0603M
footprint 0603L
footprint 0603_HV
pins: 1, 2

## RC0603FR-07680KL
designator R?  value 680k  (hidden comment: RC0603FR-07680KL)
RES, 680k ohm, 1%, 0.1W, 0603; Manufacturer: Yageo America; CompType: Resistor; Tolerance_%: 1; VDC_V: 150; Power_W: 0.1; Res_ohm: 680000; TempCo_ppm/C: 200; U/M: EA
signal-integrity model Resistor
simulation model Resistor
footprint 0603
footprint 0603M
footprint 0603L
footprint 0603_HV
pins: 1, 2

## RC0603JR-078K2L
designator R?  value 8.2k  (hidden comment: RC0603JR-078K2L)
RES, 8.2k ohm, 5%, 0.1W, 0603; Manufacturer: Yageo America; CompType: Resistor; Tolerance_%: 5; VDC_V: 50; Power_W: 0.1; Res_Ohm: 8200; Value_Code: 8k20; EIA_Code: E24
signal-integrity model Resistor
simulation model Resistor
footprint 0603
footprint 0603M
footprint 0603L
footprint 0603_HV
pins: 1, 2

## REF5025AID
designator U?
IC PREC VREF 2.5V SOIC8; Manufacturer: Texas Instruments; SymbolVersion: use current date i.e. 2008-05-20; SymbolCreator: Use LDAP id; CompType: Voltage Reference; Description: TEXAS INSTRUMENTS - REF5025AIDG4 - IC, SM, VOLT REF, 2.5V; Reference Voltage: 2.5; Dielectric: 3; No. of Pins: 8; Case Style: SOIC; Min Temperature Operating: -40
footprint M08A_L (SOIC, 8-Leads, Body 4.9x3.9mm, Pitch 1.27mm, IPC High Density)
pins: 1 DNC, 2 VIN, 3 TEMP, 4 GND, 5 TRIM/NR, 6 VOUT, 7 NC, 8 DNC

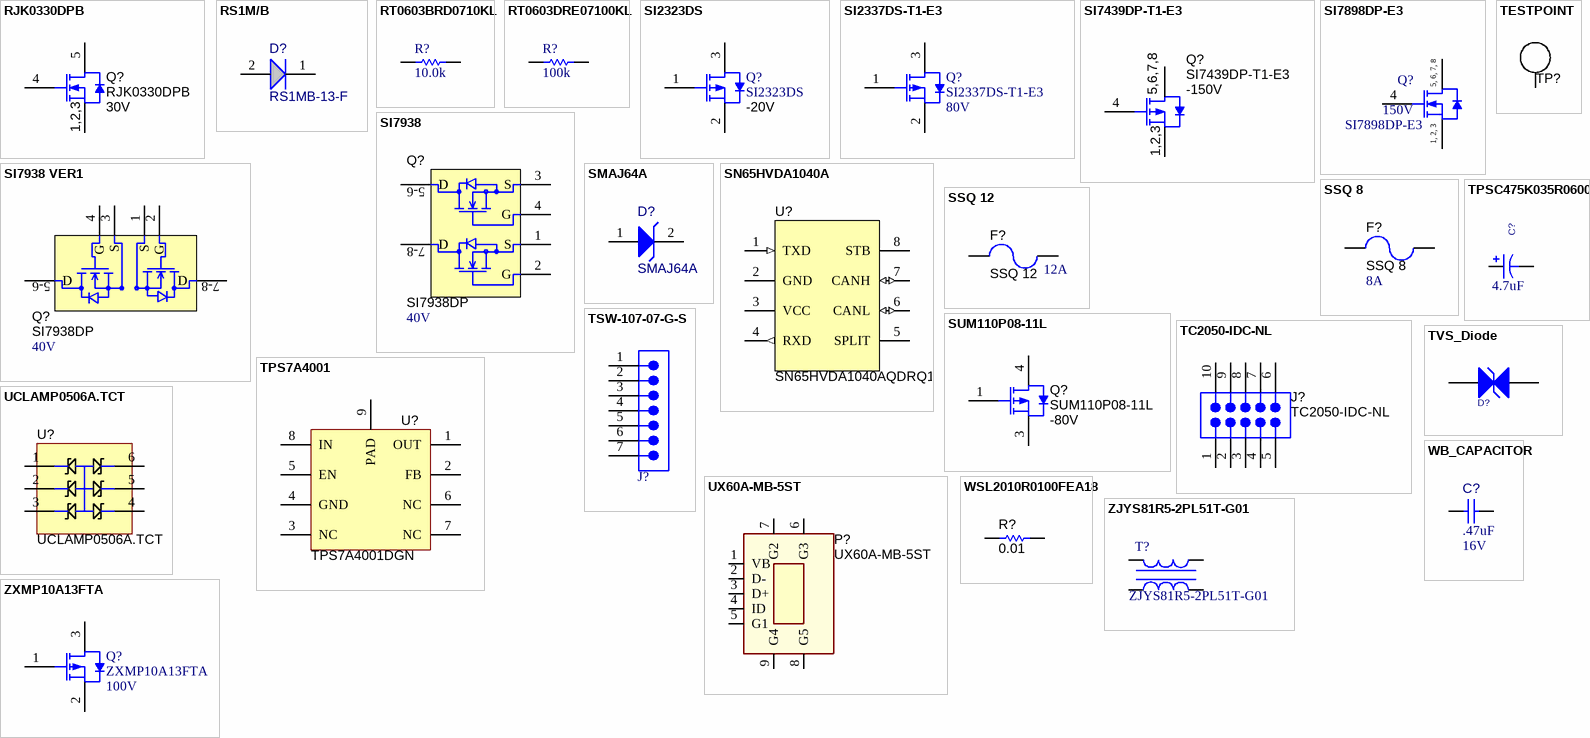
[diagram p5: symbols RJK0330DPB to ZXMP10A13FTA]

## RJK0330DPB
designator Q?  value 30V
45A, 27nC, rDS(on) @ 4.5V =0.0028 ohm; Manufacturer: Renesas; CompType: MOSFET; ChType: N; VdsMax_V: 30; Rdson45_Ohm: 0.0028; QgTyp_nC: 27; Vgs_V: 20; IdsMax_A: 45
footprint LFPAK
pins: 1 S, 2 S, 3 S, 4 G, 5 D, 6 D

## RS1M/B
designator D?, comment RS1MB-13-F
1A 1000V Recitfier; Manufacturer: Diodes Incorporated; CompType: Used in BOM report; SymbolVersion: 102209; SymbolCreator: cwiosc
footprint SMB (Molded Diode, 2-Leads, Body 5.4x3.6mm, IPC Medium Density, based on OnSemi component dimensions)
pins: 1 Cathode, 2 Anode

## RT0603BRD0710KL
designator R?  value 10.0k  (hidden comment: RT0603BRD0710KL)
0.1%, 0.1W; Manufacturer: Yageo America; CompType: Resistor; Tolerance_%: 0.1; VDC_V: 75; Res_Ohm: 10000; Value_Code: 10k0; EIA_Code: E192
signal-integrity model Resistor
simulation model Resistor
footprint 0603
footprint 0603M
footprint 0603L
pins: 1, 2

## RT0603DRE07100KL
designator R?  value 100k  (hidden comment: RT0603DRE07100KL)
0.5%, 0.1W; Manufacturer: Yageo America; CompType: Resistor; Tolerance_%: 0.5; VDC_V: 75; Power_W: 0.1; Res_Ohm: 100000; EIA_Code: E192
signal-integrity model Resistor
simulation model Resistor
footprint 0603
footprint 0603M
footprint 0603L
pins: 1, 2

## SI2323DS
designator Q?  value -20V
MOSFET, P-CH, -20V, -3.7A, SOT-23; Manufacturer: Vishay-Siliconix; ChType: P; VdsMax_V: -20; Value1: 0.031 ohm; Rdson45_Ohm: 0.031; Value2: 12.5 nC; QgTyp_nC: 12.5; Vgs_V: -8; IdsMax_A: -3.7; U/M: EA
footprint SOT-23
footprint SOT-23M
footprint SOT-23L
simulation model Si2323DS
pins: 1 G, 2 S, 3 D

## SI2337DS-T1-E3
designator Q?  value 80V
MOSFET P-CH 80V 2.2A SOT23-3; Manufacturer: Vishay/Siliconix; ChType: P; Vgs_V: +/- 20V; IdsMax_A: 2.2
footprint MF03A_N (SOT23, 3-Leads, Body 2.9x1.3mm, Pitch 0.95mm, Lead Span 2.4mm, IPC Medium Density)
pins: 1 G, 2 S, 3 D

## SI7439DP-T1-E3
designator Q?  value -150V
MOSFET, P-CH, -150V, -3A, PowerPAK SO-8; Manufacturer: Vishay-Siliconix; ChType: P; VdsMax_V: -150; Value1: ? ohm; Value2: 88 nC; QgTyp_nC: 88; Vgs_V: -20; IdsMax_A: -3; U/M: EA
footprint PowerPAK_SO-8
footprint PowerPAK_SO-8_NoVias
simulation model Si7439DP
pins: 1 S, 2 S, 3 S, 4 G, 5 D, 6 D, 7 D, 8 D, 9 D

## SI7898DP-E3
designator Q?  value 150V
3A, 17nC, rDS(on) @ 4.5V =0.076 Ohm; Manufacturer: Vishay-Siliconix; CompType: MOSFET; ChType: N; VdsMax_V: 150; Rdson45_Ohm: 0.076; QgTyp_nC: 17; Vgs_V: 20; IdsMax_A: 3
footprint PowerPAK_SO-8
footprint PowerPAK_SO-8_NoVias
simulation model Si7898DP
pins: 1 S, 2 S, 3 S, 4 G, 5 D, 6 D, 7 D, 8 D, 9 D

## SI7938
designator Q?, comment SI7938DP  value 40V
DUAL N CHANNEL MOSFET, 40V, 60A; Manufacturer: Vishay; CompType: DUAL N-Chan MOSFET 30V Rdson < 17mOhm; Power_W: 3.5W; Res_Ohm: 7mOhm
footprint POWERPAK SO-8 -Dual (Dual N-CHANNEL 40V MOSFET, POWERPAK SO-8 , VISHAY)
pins: 1 S, 2 G, 3 S, 4 G, 5 D, 6 D, 7 D, 8 D

## SI7938 VER1
designator Q?, comment SI7938DP  Value2: 40V
DUAL N CHANNEL MOSFET, 40V, 60A; Manufacturer: Vishay; CompType: DUAL N-Chan MOSFET; Power_W: 3.5W; Res_Ohm: 7mOhm
footprint POWERPAK SO-8 -Dual (Dual N-CHANNEL 40V MOSFET, POWERPAK SO-8 , VISHAY)
pins: 1 S, 2 G, 3 S, 4 G, 5 D, 6 D, 7 D, 8 D

## SMAJ64A
designator D?
DIODE TVS 64V 400W UNI 5% SMA; Manufacturer: Littlefue Inc; SymbolCreator: cwiosc
footprint SMA (Molded Diode, 2-Leads, Body 4.3x2.6mm, IPC Medium Density, based on OnSemi component dimensions and land pattern)
pins: 1 A, 2 K

## SN65HVDA1040A
designator U?, comment SN65HVDA1040AQDRQ1
CAN transceiver; Manufacturer: TI; DesignatorOriginal: U5_MOD5; A_Properties: IC CAN TRANSCEIVER 5V HS 8-SOIC; Val_4: HS; Val_3: 5V; Val_5: SO-8
footprint SO-8 (Footprint not found)
pins: 1 TXD (in), 2 GND (power), 3 VCC (power), 4 RXD (out), 5 SPLIT, 6 CANL (io), 7 CANH (io), 8 STB

## SSQ 8
designator F?  value 8A
FUSE 8A 125V 6125 FAST SSQ; Manufacturer: Bel Fuse Inc
footprint SSQ (Bel Fuse SMT Quick Acting Fuse)
pins: 1, 2

## SSQ 12
designator F?  value 12A
FUSE 12A 125V 6125 FAST SSQ; Manufacturer: Bel Fuse Inc
footprint SSQ (Bel Fuse SMT Quick Acting Fuse)
pins: 1, 2

## SUM110P08-11L
designator Q?  value -80V
MOSFET, P-CH, -80V, -23.5A, DDPAK; Manufacturer: Vishay-Siliconix; ChType: P; VdsMax_V: -80; Value1: 0.012 ohm; Rdson45_Ohm: 0.012; Value2: 85 nC; QgTyp_nC: 85; Vgs_V: -20; IdsMax_A: -23.5
footprint DDPAK
pins: 1 G, 3 S, 4 D

## TC2050-IDC-NL
designator J?
TC2050 plug of nails cable; Manufacturer: Tag-Connect; SymbolVersion: use current date i.e. 2008-05-20; SymbolCreator: Use LDAP id; CompType: Connector
footprint TC2050-IDC-NL-10
pins: 1, 2, 3, 4, 5, 6, 7, 8, 9, 10

## TESTPOINT
designator TP?  (value not drawn)  (no BOM)
TEST POINT.  No entry in BOM.; PartNumber: Used in BOM report
footprint TESTPOINT
pins: 1

## TPS7A4001
designator U?, comment TPS7A4001DGN
VREG, LDO, ADJ, 50mA, MSOP8; Manufacturer: TI; SymbolCreator: CSXHSC; U/M: EA
footprint MUY08A_L (TSOP, 8-Leads, Body 3x3mm, Pitch 0.65mm, Exposed Pad, IPC High Density)
footprint MUY08A_N (TSOP, 8-Leads, Body 3x3mm, Pitch 0.65mm, Exposed Pad, IPC Medium Density)
pins: 1 OUT (power), 2 FB, 3 NC, 4 GND (power), 5 EN, 6 NC, 7 NC, 8 IN (power), 9 PAD (power)

## TPSC475K035R0600
designator C?  value 4.7uF  (hidden comment: TPSC475K035R0600)
TA, 35V, 10%, 0.6Ohm ESR; Manufacturer: AVX; CompType: Capacitor; Cap_Case: C; ESR_Ohm: 0.6; IRMS_A: 0.385; Polarized: Y; TaMax_C: 125; TaMin_C: -55; Tolerance_%: 10; VDC_V: 35; Cap_F: 4.7E-6; Dielectric: TPS
signal-integrity model Cap
simulation model Cap
footprint 6032-28 (Medium Density IPC based on SM-782 data, section 8.4)
pins: 1 +, 2 -

## TSW-107-07-G-S
designator J?  (value not drawn)
Header, TH, 100mil, 1x7, Gold plated, 230 mil above insulator; Manufacturer: Samtec Inc.
footprint TSW-107-XX-XXX-S (2.54mm pitch, 7 pin, terminal strip; straight, single row)
pins: 1, 2, 3, 4, 5, 6, 7

## TVS_Diode
designator D?, comment PGB0010603MR  (value not drawn)
Transient Voltage Suppression Diode; Manufacturer: Littlefuse; CompType: Transorb
footprint 0603L
pins: 1 A, 2 K

## UCLAMP0506A.TCT
designator U?
TVS ESD BIDIRECT 5V SOT-666; Manufacturer: SemTech; SymbolVersion: use current date i.e. 2008-05-20; SymbolCreator: CSXHSC
footprint MF06A_N (SOT23, 6-Leads, Body 2.9x1.6mm, Pitch 0.95mm, Lead Span 2.8mm, IPC Medium Density)
pins: 1, 2, 3, 4, 5, 6

## UX60A-MB-5ST
designator P?
CONN RECEPT MINI USB2.0 5POS; Manufacturer: Hirose; SymbolVersion: use current date i.e. 2008-05-20; SymbolCreator: Use LDAP id; CompType: Connector
footprint UX60A-MB-5ST (USB mini-B Right Angle without positioning post)
pins: 1 VB, 2 D-, 3 D+, 4 ID, 5 G1, 6 G3, 7 G2, 8 G5, 9 G4

## WB_CAPACITOR
designator C?, comment Value1: .47uF  Value2: 16V  (hidden comment: 0.47, 16V)
Manufacturer: Taiyo Yuden; PartNumber: EMK107B7474KA-T; CompType: Capacitor; Value3: X7R; A_Properties: CAP CER .47UF 16V X7R 0603
simulation model Capacitor
footprint 0603 (0603 from SM-752 data)
footprint 0402 (0402 from SM-752 data)
footprint 0805 (0805 from SM-752 data)
footprint 1206 (1206 from SM-752 data)
footprint 0201 (Data from Panasonic ERJ resistor datasheet dated February 2006)
footprint 0603L (0603 from SM-752 data)
footprint 0402L (0402 from SM-752 data)
footprint 0805L (0805 from SM-752 data)
footprint 1206L (1206 from SM-752 data)
footprint 0603M (0603 from SM-752 data)
footprint 0402M (0402 from SM-752 data)
footprint 0805M (0805 from SM-752 data)
footprint 1206M (1206 from SM-752 data)
footprint 0603ST
pins: 1, 2

## WSL2010R0100FEA18
designator R?  value 0.01  (hidden comment: WSL2010R0100FEA18)
RES, 0.01 ohm, 1%, 1W, 2010 SMD; Manufacturer: Vishay-Dale; CompType: Resistor; Tolerance_%: 1; Value_Code: R010; EIA_Code: E96
signal-integrity model Resistor
simulation model Resistor
footprint 2010M
footprint 2010L
footprint 2010
pins: 1, 2

## ZJYS81R5-2PL51T-G01
designator T?
CHOKE COMM MODE 1000 OHM .5A SMD; Manufacturer: TDK; CompType: Common Mode Choke
footprint TDK Choke (TDK Common Mode Choke)
pins: 1, 2, 3, 4

## ZXMP10A13FTA
designator Q?  value 100V
MOSFET P-CH 100V 700MA SOT23-3; Manufacturer: Diodes/Zetex; ChType: P; Vgs_V: +/- 20V; IdsMax_A: -3.1
footprint MF03A_N (SOT23, 3-Leads, Body 2.9x1.3mm, Pitch 0.95mm, Lead Span 2.4mm, IPC Medium Density)
pins: 1 G, 2 S, 3 D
